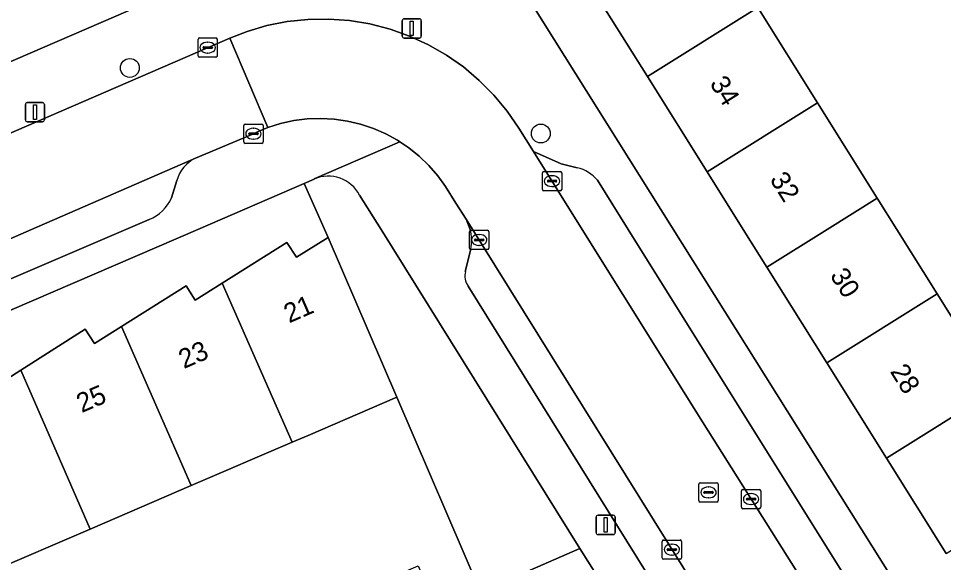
# Model space of a CAD drawing. Extents: x 159352 to 160617, y 385888 to 387323.
# Drawn here: x 159685.66 to 159733.61, y 386232.72 to 386260.95 of the extents above; entities that cross this region are included whole.
import ezdxf

# ---------------------------------------------------------------- set-up
doc = ezdxf.new("R2010")
doc.units = 0
for name, color, linetype in [('IMGEO_Boom', 7, 'Continuous'), ('IMGEO_Erf', 7, 'Continuous'), ('IMGEO_Groenvoorziening', 7, 'Continuous'), ('IMGEO_Kolk', 7, 'Continuous'), ('IMGEO_Lichtmast', 7, 'Continuous'), ('IMGEO_Pand', 7, 'Continuous'), ('IMGEO_Pand_nummerreeks', 7, 'Continuous'), ('IMGEO_Parkeervlak_open', 7, 'Continuous'), ('IMGEO_Rijbaan_lokaal_open', 7, 'Continuous'), ('IMGEO_Rioolput', 7, 'Continuous'), ('IMGEO_Voetpad_open', 7, 'Continuous')]:
    doc.layers.add(name, color=color, linetype=linetype)

msp = doc.modelspace()

# ---------------------------------------------------------------- linework, layer by layer
at = {"layer": 'IMGEO_Boom'}
for centre in [(159691.433, 386258.38), (159712.735, 386254.974)]:
    msp.add_circle(centre, 0.489, dxfattribs=at)
at = {"layer": 'IMGEO_Erf'}
for points in [[(159684.675, 386306.593), (159662.967, 386297.224), (159666.737, 386288.494), (159668.247, 386284.999), (159665.868, 386283.972), (159666.716, 386282.012), (159669.102, 386283.045), (159670.095, 386280.751), (159671.505, 386277.494), (159672.931, 386274.199), (159673.89, 386271.984), (159671.504, 386270.951), (159672.472, 386268.715), (159674.858, 386269.748), (159676.268, 386266.491), (159677.694, 386263.196), (159675.308, 386262.163), (159678.131, 386255.638), (159699.462, 386264.867)], [(159747.163, 386257.648), (159744.743, 386256.118), (159742.651, 386259.427), (159740.817, 386262.329), (159743.237, 386263.859), (159740.975, 386267.538), (159738.555, 386266.008), (159736.465, 386269.315), (159734.629, 386272.219), (159737.049, 386273.749), (159735.739, 386275.442), (159732.563, 386280.372), (159730.296, 386278.912), (159730.161, 386279.136), (159709.565, 386266.048), (159737.124, 386222.064)], [(159733.75, 386233.191), (159730.653, 386238.14), (159727.557, 386243.087), (159724.456, 386248.041), (159723.23, 386250), (159721.363, 386252.982), (159718.266, 386257.931), (159715.091, 386263.004), (159719.33, 386265.657), (159720.811, 386266.583), (159721.092, 386266.135), (159723.603, 386267.744), (159726.269, 386263.593), (159723.762, 386261.867), (159723.986, 386261.509), (159727.082, 386256.56), (159730.174, 386251.619), (159731.187, 386250), (159733.275, 386246.664), (159736.37, 386241.716)], [(159684.366, 386241.806), (159685.781, 386242.704), (159689.113, 386244.818), (159689.592, 386244.075), (159690.997, 386244.961), (159694.346, 386247.073), (159694.816, 386246.331), (159696.21, 386247.21), (159699.566, 386249.327), (159700.068, 386248.566), (159701.706, 386249.577), (159700.471, 386252.381), (159694.949, 386250), (159599.575, 386208.876)], [(159678.381, 386217.729), (159690.481, 386222.933), (159689.474, 386225.274), (159692.711, 386226.667), (159695.916, 386228.046), (159696.923, 386225.705), (159700.95, 386227.437), (159699.943, 386229.778), (159703.257, 386231.204), (159706.385, 386232.55), (159707.392, 386230.209), (159709.611, 386231.2), (159705.267, 386241.292), (159700.675, 386239.316), (159699.843, 386238.958), (159694.613, 386236.708), (159689.374, 386234.454), (159684.117, 386232.192)]]:
    msp.add_lwpolyline(points, dxfattribs=at)
at = {"layer": 'IMGEO_Groenvoorziening'}
msp.add_lwpolyline([(159700.986, 386252.613), (159700.471, 386252.381), (159701.706, 386249.577), (159705.267, 386241.292), (159709.611, 386231.2), (159714.762, 386233.446), (159704.452, 386250), (159703.344, 386251.779)], dxfattribs=at)
msp.add_arc((159701.713, 386250.919), 1.844, 27.8113, 113.2324, dxfattribs=at)
at = {"layer": 'IMGEO_Kolk'}
for p, q in [((159694.966, 386259.007), (159694.966, 386259.859)), ((159695.041, 386259.933), (159695.893, 386259.933)), ((159695.967, 386259.859), (159695.967, 386259.007)), ((159695.225, 386259.427), (159695.225, 386259.439)), ((159695.663, 386259.39), (159695.265, 386259.39)), ((159695.268, 386259.476), (159695.666, 386259.476)), ((159695.454, 386259.713), (159695.479, 386259.713)), ((159695.709, 386259.439), (159695.709, 386259.427)), ((159695.893, 386258.933), (159695.041, 386258.933)), ((159695.477, 386259.153), (159695.452, 386259.153)), ((159697.339, 386254.541), (159697.339, 386255.393)), ((159697.414, 386255.467), (159698.266, 386255.467)), ((159697.827, 386255.247), (159697.852, 386255.247)), ((159698.34, 386255.393), (159698.34, 386254.541)), ((159697.598, 386254.961), (159697.598, 386254.973)), ((159698.036, 386254.924), (159697.638, 386254.924)), ((159697.641, 386255.01), (159698.039, 386255.01)), ((159697.85, 386254.687), (159697.825, 386254.687)), ((159698.082, 386254.973), (159698.082, 386254.961)), ((159698.266, 386254.467), (159697.414, 386254.467)), ((159712.817, 386252.08), (159712.817, 386252.932)), ((159712.892, 386253.006), (159713.744, 386253.006)), ((159713.305, 386252.786), (159713.33, 386252.786)), ((159713.818, 386252.932), (159713.818, 386252.08)), ((159713.076, 386252.5), (159713.076, 386252.512)), ((159713.514, 386252.463), (159713.116, 386252.463)), ((159713.119, 386252.549), (159713.517, 386252.549)), ((159713.328, 386252.226), (159713.303, 386252.226)), ((159713.56, 386252.512), (159713.56, 386252.5)), ((159713.744, 386252.006), (159712.892, 386252.006)), ((159709.04, 386249.028), (159709.04, 386249.88)), ((159709.115, 386249.954), (159709.967, 386249.954)), ((159710.041, 386249.88), (159710.041, 386249.028)), ((159709.299, 386249.448), (159709.299, 386249.46)), ((159709.737, 386249.411), (159709.339, 386249.411)), ((159709.342, 386249.497), (159709.74, 386249.497)), ((159709.528, 386249.734), (159709.553, 386249.734)), ((159709.783, 386249.46), (159709.783, 386249.448)), ((159709.967, 386248.954), (159709.115, 386248.954)), ((159709.551, 386249.174), (159709.526, 386249.174)), ((159723.134, 386235.585), (159723.134, 386236.437)), ((159723.209, 386236.511), (159724.061, 386236.511)), ((159724.135, 386236.437), (159724.135, 386235.585)), ((159723.393, 386236.005), (159723.393, 386236.017)), ((159723.831, 386235.968), (159723.433, 386235.968)), ((159723.436, 386236.054), (159723.834, 386236.054)), ((159723.622, 386236.291), (159723.647, 386236.291)), ((159723.877, 386236.017), (159723.877, 386236.005)), ((159724.061, 386235.511), (159723.209, 386235.511)), ((159723.645, 386235.731), (159723.62, 386235.731)), ((159719.027, 386232.96), (159719.027, 386233.812)), ((159719.102, 386233.886), (159719.954, 386233.886)), ((159719.515, 386233.666), (159719.54, 386233.666)), ((159720.028, 386233.812), (159720.028, 386232.96)), ((159719.286, 386233.38), (159719.286, 386233.392)), ((159719.724, 386233.343), (159719.326, 386233.343)), ((159719.329, 386233.429), (159719.727, 386233.429)), ((159719.538, 386233.106), (159719.513, 386233.106)), ((159719.77, 386233.392), (159719.77, 386233.38)), ((159719.954, 386232.886), (159719.102, 386232.886))]:
    msp.add_line(p, q, dxfattribs=at)
for points in [[(159694.966, 386259.007), (159694.966, 386259.859)], [(159695.041, 386259.933), (159695.893, 386259.933)], [(159695.967, 386259.859), (159695.967, 386259.007)], [(159695.893, 386258.933), (159695.041, 386258.933)], [(159697.339, 386254.541), (159697.339, 386255.393)], [(159697.414, 386255.467), (159698.266, 386255.467)], [(159698.34, 386255.393), (159698.34, 386254.541)], [(159698.266, 386254.467), (159697.414, 386254.467)], [(159712.817, 386252.08), (159712.817, 386252.932)], [(159712.892, 386253.006), (159713.744, 386253.006)], [(159713.818, 386252.932), (159713.818, 386252.08)], [(159713.744, 386252.006), (159712.892, 386252.006)], [(159709.04, 386249.028), (159709.04, 386249.88)], [(159709.115, 386249.954), (159709.967, 386249.954)], [(159710.041, 386249.88), (159710.041, 386249.028)], [(159709.967, 386248.954), (159709.115, 386248.954)], [(159723.134, 386235.585), (159723.134, 386236.437)], [(159723.209, 386236.511), (159724.061, 386236.511)], [(159724.135, 386236.437), (159724.135, 386235.585)], [(159724.061, 386235.511), (159723.209, 386235.511)], [(159719.027, 386232.96), (159719.027, 386233.812)], [(159719.102, 386233.886), (159719.954, 386233.886)], [(159720.028, 386233.812), (159720.028, 386232.96)], [(159719.954, 386232.886), (159719.102, 386232.886)]]:
    msp.add_lwpolyline(points, dxfattribs=at)
for centre, radius, start, end in [((159695.043, 386259.857), 0.0765, 91.552, 178.448), ((159695.043, 386259.857), 0.0765, 91.552, 178.448), ((159695.891, 386259.857), 0.0765, 1.552, 88.448), ((159695.891, 386259.857), 0.0765, 1.552, 88.448), ((159695.265, 386259.436), 0.0403, 85.8775, 175.7526), ((159695.262, 386259.426), 0.0366, 178.938, 274.7102), ((159695.666, 386259.433), 0.043, 264.8664, 352.4533), ((159695.67, 386259.438), 0.0386, 1.7309, 96.639), ((159695.043, 386259.009), 0.0765, 181.552, 268.448), ((159695.043, 386259.009), 0.0765, 181.552, 268.448), ((159695.891, 386259.009), 0.0765, 271.552, 358.448), ((159695.891, 386259.009), 0.0765, 271.552, 358.448), ((159697.416, 386255.391), 0.0765, 91.552, 178.448), ((159697.416, 386255.391), 0.0765, 91.552, 178.448), ((159698.264, 386255.391), 0.0765, 1.552, 88.448), ((159698.264, 386255.391), 0.0765, 1.552, 88.448), ((159697.638, 386254.97), 0.0403, 85.8775, 175.7526), ((159697.635, 386254.96), 0.0366, 178.938, 274.7102), ((159698.039, 386254.967), 0.043, 264.8664, 352.4533), ((159698.043, 386254.972), 0.0386, 1.7309, 96.639), ((159697.416, 386254.543), 0.0765, 181.552, 268.448), ((159697.416, 386254.543), 0.0765, 181.552, 268.448), ((159698.264, 386254.543), 0.0765, 271.552, 358.448), ((159698.264, 386254.543), 0.0765, 271.552, 358.448), ((159712.894, 386252.93), 0.0765, 91.552, 178.448), ((159712.894, 386252.93), 0.0765, 91.552, 178.448), ((159713.742, 386252.93), 0.0765, 1.552, 88.448), ((159713.742, 386252.93), 0.0765, 1.552, 88.448), ((159713.116, 386252.509), 0.0403, 85.8775, 175.7526), ((159713.113, 386252.499), 0.0366, 178.938, 274.7102), ((159713.517, 386252.506), 0.043, 264.8664, 352.4533), ((159713.521, 386252.511), 0.0386, 1.7309, 96.639), ((159712.894, 386252.082), 0.0765, 181.552, 268.448), ((159712.894, 386252.082), 0.0765, 181.552, 268.448), ((159713.742, 386252.082), 0.0765, 271.552, 358.448), ((159713.742, 386252.082), 0.0765, 271.552, 358.448), ((159709.117, 386249.878), 0.0765, 91.552, 178.448), ((159709.117, 386249.878), 0.0765, 91.552, 178.448), ((159709.965, 386249.878), 0.0765, 1.552, 88.448), ((159709.965, 386249.878), 0.0765, 1.552, 88.448), ((159709.339, 386249.457), 0.0403, 85.8775, 175.7526), ((159709.336, 386249.447), 0.0366, 178.938, 274.7102), ((159709.74, 386249.454), 0.043, 264.8664, 352.4533), ((159709.744, 386249.459), 0.0386, 1.7309, 96.639), ((159709.117, 386249.03), 0.0765, 181.552, 268.448), ((159709.117, 386249.03), 0.0765, 181.552, 268.448), ((159709.965, 386249.03), 0.0765, 271.552, 358.448), ((159709.965, 386249.03), 0.0765, 271.552, 358.448), ((159723.211, 386236.435), 0.0765, 91.552, 178.448), ((159723.211, 386236.435), 0.0765, 91.552, 178.448), ((159724.059, 386236.435), 0.0765, 1.552, 88.448), ((159724.059, 386236.435), 0.0765, 1.552, 88.448), ((159723.433, 386236.014), 0.0403, 85.8775, 175.7526), ((159723.43, 386236.004), 0.0366, 178.938, 274.7102), ((159723.834, 386236.011), 0.043, 264.8664, 352.4533), ((159723.838, 386236.016), 0.0386, 1.7309, 96.639), ((159723.211, 386235.587), 0.0765, 181.552, 268.448), ((159723.211, 386235.587), 0.0765, 181.552, 268.448), ((159724.059, 386235.587), 0.0765, 271.552, 358.448), ((159724.059, 386235.587), 0.0765, 271.552, 358.448), ((159719.104, 386233.81), 0.0765, 91.552, 178.448), ((159719.104, 386233.81), 0.0765, 91.552, 178.448), ((159719.952, 386233.81), 0.0765, 1.552, 88.448), ((159719.952, 386233.81), 0.0765, 1.552, 88.448), ((159719.326, 386233.389), 0.0403, 85.8775, 175.7526), ((159719.323, 386233.379), 0.0366, 178.938, 274.7102), ((159719.727, 386233.386), 0.043, 264.8664, 352.4533), ((159719.731, 386233.391), 0.0386, 1.7309, 96.639), ((159719.104, 386232.962), 0.0765, 181.552, 268.448), ((159719.104, 386232.962), 0.0765, 181.552, 268.448), ((159719.952, 386232.962), 0.0765, 271.552, 358.448), ((159719.952, 386232.962), 0.0765, 271.552, 358.448)]:
    msp.add_arc(centre, radius, start, end, dxfattribs=at)
for centre, major_axis, ratio, start_param, end_param in [((159695.453, 386259.433), (-0.387, 0.002), 0.722429, 4.712389, 7.853982), ((159695.478, 386259.433), (-0.39, 0.002), 0.717154, 1.570796, 4.712389), ((159697.826, 386254.967), (-0.387, 0.002), 0.722429, 4.712389, 7.853982), ((159697.851, 386254.967), (-0.39, 0.002), 0.717154, 1.570796, 4.712389), ((159713.304, 386252.506), (-0.387, 0.002), 0.722429, 4.712389, 7.853982), ((159713.329, 386252.506), (-0.39, 0.002), 0.717154, 1.570796, 4.712389), ((159709.527, 386249.454), (-0.387, 0.002), 0.722429, 4.712389, 7.853982), ((159709.552, 386249.454), (-0.39, 0.002), 0.717154, 1.570796, 4.712389), ((159723.621, 386236.011), (-0.387, 0.002), 0.722429, 4.712389, 7.853982), ((159723.646, 386236.011), (-0.39, 0.002), 0.717154, 1.570796, 4.712389), ((159719.514, 386233.386), (-0.387, 0.002), 0.722429, 4.712389, 7.853982), ((159719.539, 386233.386), (-0.39, 0.002), 0.717154, 1.570796, 4.712389)]:
    msp.add_ellipse(centre, major_axis=major_axis, ratio=ratio, start_param=start_param, end_param=end_param, dxfattribs=at)
at = {"layer": 'IMGEO_Lichtmast'}
for p, q in [((159705.551, 386260.03), (159705.551, 386260.83)), ((159705.551, 386260.83), (159705.551, 386260.03)), ((159705.651, 386260.93), (159706.441, 386260.93)), ((159706.441, 386260.93), (159705.651, 386260.93)), ((159706.541, 386260.83), (159706.541, 386260.03)), ((159706.541, 386260.03), (159706.541, 386260.83)), ((159706.441, 386259.93), (159705.651, 386259.93)), ((159705.651, 386259.93), (159706.441, 386259.93)), ((159686.015, 386255.685), (159686.015, 386256.485)), ((159686.015, 386256.485), (159686.015, 386255.685)), ((159686.115, 386256.585), (159686.905, 386256.585)), ((159686.905, 386256.585), (159686.115, 386256.585)), ((159687.005, 386256.485), (159687.005, 386255.685)), ((159687.005, 386255.685), (159687.005, 386256.485)), ((159686.905, 386255.585), (159686.115, 386255.585)), ((159686.115, 386255.585), (159686.905, 386255.585)), ((159715.601, 386234.271), (159715.601, 386235.071)), ((159715.601, 386235.071), (159715.601, 386234.271)), ((159715.701, 386235.171), (159716.491, 386235.171)), ((159716.491, 386235.171), (159715.701, 386235.171)), ((159716.591, 386235.071), (159716.591, 386234.271)), ((159716.591, 386234.271), (159716.591, 386235.071)), ((159716.491, 386234.171), (159715.701, 386234.171)), ((159715.701, 386234.171), (159716.491, 386234.171))]:
    msp.add_line(p, q, dxfattribs=at)
for points in [[(159705.971, 386260.805), (159706.121, 386260.805), (159706.121, 386260.055), (159705.971, 386260.055), (159705.971, 386260.805)], [(159686.435, 386256.46), (159686.585, 386256.46), (159686.585, 386255.71), (159686.435, 386255.71), (159686.435, 386256.46)], [(159716.021, 386235.046), (159716.171, 386235.046), (159716.171, 386234.296), (159716.021, 386234.296), (159716.021, 386235.046)]]:
    msp.add_lwpolyline(points, dxfattribs=at)
for centre, start, end in [((159705.651, 386260.83), 90, 180), ((159705.651, 386260.83), 90, 180), ((159706.441, 386260.83), 0, 90), ((159706.441, 386260.83), 360, 90), ((159705.651, 386260.03), 180, 270), ((159705.651, 386260.03), 180, 270), ((159706.441, 386260.03), 270, 0), ((159706.441, 386260.03), 270, 0), ((159686.115, 386256.485), 90, 180), ((159686.115, 386256.485), 90, 180), ((159686.905, 386256.485), 0, 90), ((159686.905, 386256.485), 360, 90), ((159686.115, 386255.685), 180, 270), ((159686.115, 386255.685), 180, 270), ((159686.905, 386255.685), 270, 0), ((159686.905, 386255.685), 270, 0), ((159715.701, 386235.071), 90, 180), ((159715.701, 386235.071), 90, 180), ((159716.491, 386235.071), 0, 90), ((159716.491, 386235.071), 360, 90), ((159715.701, 386234.271), 180, 270), ((159715.701, 386234.271), 180, 270), ((159716.491, 386234.271), 270, 0), ((159716.491, 386234.271), 270, 0)]:
    msp.add_arc(centre, 0.1, start, end, dxfattribs=at)
at = {"layer": 'IMGEO_Pand'}
for points in [[(159721.092, 386266.135), (159720.811, 386266.583), (159719.33, 386265.657), (159715.091, 386263.004), (159718.266, 386257.931), (159723.986, 386261.509), (159723.762, 386261.867), (159726.269, 386263.593), (159723.603, 386267.744)], [(159718.266, 386257.931), (159721.363, 386252.982), (159727.082, 386256.56), (159723.986, 386261.509)], [(159727.587, 386250), (159730.174, 386251.619), (159727.082, 386256.56), (159721.363, 386252.982), (159723.23, 386250), (159724.456, 386248.041)], [(159724.456, 386248.041), (159727.557, 386243.087), (159733.275, 386246.664), (159731.187, 386250), (159730.174, 386251.619), (159727.587, 386250)], [(159701.706, 386249.577), (159700.068, 386248.566), (159699.566, 386249.327), (159696.21, 386247.21), (159699.843, 386238.958), (159700.675, 386239.316), (159705.267, 386241.292)], [(159696.21, 386247.21), (159694.816, 386246.331), (159694.346, 386247.073), (159690.997, 386244.961), (159694.613, 386236.708), (159699.843, 386238.958)], [(159727.557, 386243.087), (159730.653, 386238.14), (159736.37, 386241.716), (159733.275, 386246.664)], [(159690.997, 386244.961), (159689.592, 386244.075), (159689.113, 386244.818), (159685.781, 386242.704), (159689.374, 386234.454), (159694.613, 386236.708)], [(159685.781, 386242.704), (159684.366, 386241.806), (159683.888, 386242.553), (159680.559, 386240.462), (159684.117, 386232.192), (159689.374, 386234.454)], [(159730.653, 386238.14), (159733.75, 386233.191), (159739.467, 386236.768), (159736.37, 386241.716)]]:
    msp.add_lwpolyline(points, close=True, dxfattribs=at)
at = {"layer": 'IMGEO_Parkeervlak_open'}
for points in [[(159694.84, 386253.699), (159686.334, 386250), (159681.73, 386247.998), (159678.398, 386246.561), (159679.147, 386244.823), (159691.231, 386250)], [(159714.626, 386253.203), (159713.789, 386253.396), (159712.353, 386254.051), (159714.88, 386250), (159721.113, 386240.01), (159731.901, 386222.896)], [(159693.593, 386251.643), (159693.863, 386252.544)], [(159731.921, 386226.535), (159717.271, 386250), (159715.678, 386252.552)], [(159691.231, 386250), (159692.435, 386250.516)], [(159708.862, 386250.524), (159709.076, 386250)], [(159728.997, 386218.179), (159728.35, 386219.221), (159708.862, 386250.524)], [(159709.103, 386248.984), (159708.823, 386247.818)], [(159708.962, 386247.06), (159725.996, 386219.672)]]:
    msp.add_lwpolyline(points, dxfattribs=at)
for centre, radius, start, end in [((159695.672, 386252.005), 1.887, 116.1468, 163.3983), ((159714.124, 386251.217), 2.049, 40.6761, 75.8237), ((159691.642, 386252.489), 2.126, 291.8918, 336.5537), ((159706.951, 386249.435), 2.199, 348.159, 14.8855), ((159709.793, 386247.604), 0.993, 167.5695, 213.2131)]:
    msp.add_arc(centre, radius, start, end, dxfattribs=at)
at = {"layer": 'IMGEO_Rijbaan_lokaal_open'}
for points in [[(159731.901, 386222.896), (159721.113, 386240.01), (159714.88, 386250), (159712.353, 386254.051), (159711.601, 386255.256), (159710.991, 386256.142), (159710.305, 386256.971), (159709.547, 386257.735), (159708.724, 386258.428), (159707.842, 386259.044), (159706.909, 386259.58), (159705.931, 386260.03), (159704.918, 386260.391), (159703.876, 386260.66), (159702.814, 386260.834), (159701.741, 386260.914), (159700.665, 386260.897), (159699.595, 386260.784), (159698.539, 386260.576), (159697.507, 386260.274), (159696.609, 386259.927), (159698.584, 386255.284), (159699.25, 386255.494), (159699.932, 386255.644), (159700.625, 386255.732), (159701.323, 386255.757), (159702.02, 386255.721), (159702.711, 386255.622), (159703.391, 386255.462), (159704.054, 386255.242), (159704.694, 386254.963), (159705.307, 386254.628), (159705.433, 386254.544), (159705.887, 386254.24), (159706.431, 386253.802), (159706.933, 386253.317), (159707.39, 386252.789), (159707.798, 386252.222), (159708.336, 386251.369), (159708.862, 386250.524), (159728.35, 386219.221)], [(159664.679, 386240.646), (159674.955, 386245.077), (159678.398, 386246.561), (159681.73, 386247.998), (159686.334, 386250), (159694.84, 386253.699), (159697.839, 386254.968), (159698.076, 386255.078), (159698.584, 386255.284), (159696.609, 386259.927), (159678.479, 386252.07), (159675.018, 386250.574), (159673.692, 386250), (159656.655, 386242.648), (159656.656, 386242.615), (159641.394, 386236.065)]]:
    msp.add_lwpolyline(points, dxfattribs=at)
at = {"layer": 'IMGEO_Rioolput'}
for p, q in [((159721.004, 386236.857), (159721.856, 386236.857)), ((159720.929, 386235.931), (159720.929, 386236.783)), ((159721.188, 386236.351), (159721.188, 386236.363)), ((159721.231, 386236.4), (159721.629, 386236.4)), ((159721.417, 386236.637), (159721.442, 386236.637)), ((159721.672, 386236.363), (159721.672, 386236.351)), ((159721.93, 386236.783), (159721.93, 386235.931)), ((159721.626, 386236.314), (159721.228, 386236.314)), ((159721.44, 386236.077), (159721.415, 386236.077)), ((159721.856, 386235.857), (159721.004, 386235.857))]:
    msp.add_line(p, q, dxfattribs=at)
for points in [[(159721.004, 386236.857), (159721.856, 386236.857)], [(159720.929, 386235.931), (159720.929, 386236.783)], [(159721.93, 386236.783), (159721.93, 386235.931)], [(159721.856, 386235.857), (159721.004, 386235.857)]]:
    msp.add_lwpolyline(points, dxfattribs=at)
for centre, radius, start, end in [((159721.006, 386236.781), 0.0765, 91.552, 178.448), ((159721.006, 386236.781), 0.0765, 91.552, 178.448), ((159721.854, 386236.781), 0.0765, 1.552, 88.448), ((159721.854, 386236.781), 0.0765, 1.552, 88.448), ((159721.228, 386236.36), 0.0403, 85.8775, 175.7526), ((159721.225, 386236.35), 0.0366, 178.938, 274.7102), ((159721.629, 386236.357), 0.043, 264.8664, 352.4533), ((159721.633, 386236.362), 0.0386, 1.7309, 96.639), ((159721.006, 386235.933), 0.0765, 181.552, 268.448), ((159721.006, 386235.933), 0.0765, 181.552, 268.448), ((159721.854, 386235.933), 0.0765, 271.552, 358.448), ((159721.854, 386235.933), 0.0765, 271.552, 358.448)]:
    msp.add_arc(centre, radius, start, end, dxfattribs=at)
for centre, major_axis, ratio, start_param, end_param in [((159721.416, 386236.357), (-0.387, 0.002), 0.722429, 4.712389, 7.853982), ((159721.441, 386236.357), (-0.39, 0.002), 0.717154, 1.570796, 4.712389)]:
    msp.add_ellipse(centre, major_axis=major_axis, ratio=ratio, start_param=start_param, end_param=end_param, dxfattribs=at)
at = {"layer": 'IMGEO_Voetpad_open'}
for points in [[(159709.565, 386266.048), (159709.001, 386266.959), (159708.189, 386268.272), (159699.462, 386264.867), (159678.131, 386255.638), (159676.842, 386255.08), (159665.102, 386250), (159655.763, 386245.959), (159655.677, 386245.872), (159650.446, 386243.55)], [(159737.124, 386222.064), (159709.565, 386266.048)], [(159678.479, 386252.07), (159696.609, 386259.927), (159697.507, 386260.274), (159698.539, 386260.576), (159699.595, 386260.784), (159700.665, 386260.897), (159701.741, 386260.914), (159702.814, 386260.834), (159703.876, 386260.66), (159704.918, 386260.391), (159705.931, 386260.03), (159706.909, 386259.58), (159707.842, 386259.044), (159708.724, 386258.428), (159709.547, 386257.735), (159710.305, 386256.971), (159710.991, 386256.142), (159711.601, 386255.256), (159712.353, 386254.051), (159713.789, 386253.396), (159714.626, 386253.203)], [(159705.433, 386254.544), (159705.307, 386254.628), (159704.694, 386254.963), (159704.054, 386255.242), (159703.391, 386255.462), (159702.711, 386255.622), (159702.02, 386255.721), (159701.323, 386255.757), (159700.625, 386255.732), (159699.932, 386255.644), (159699.25, 386255.494), (159698.584, 386255.284), (159698.076, 386255.078), (159697.839, 386254.968), (159694.84, 386253.699)], [(159599.575, 386208.876), (159694.949, 386250), (159700.471, 386252.381), (159700.986, 386252.613), (159700.992, 386252.628), (159705.433, 386254.544)], [(159708.336, 386251.369), (159707.798, 386252.222), (159707.39, 386252.789), (159706.933, 386253.317), (159706.431, 386253.802), (159705.887, 386254.24), (159705.433, 386254.544), (159700.992, 386252.628), (159700.986, 386252.613)], [(159693.863, 386252.544), (159693.593, 386251.643)], [(159715.678, 386252.552), (159717.271, 386250), (159731.921, 386226.535)], [(159703.344, 386251.779), (159704.452, 386250), (159714.762, 386233.446), (159715.586, 386232.137), (159724.116, 386218.496), (159725.996, 386219.672), (159708.962, 386247.06)], [(159709.076, 386250), (159708.862, 386250.524), (159708.336, 386251.369)], [(159692.435, 386250.516), (159691.231, 386250), (159679.147, 386244.823), (159679.332, 386244.41), (159675.869, 386242.916), (159675.708, 386243.331), (159660.393, 386236.7), (159660.572, 386236.289), (159657.111, 386234.796), (159656.936, 386235.216), (159641.701, 386228.667), (159641.868, 386228.269), (159638.432, 386226.756), (159638.262, 386227.153), (159623.466, 386220.812), (159623.657, 386220.412), (159620.194, 386218.926), (159620.013, 386219.343), (159605.603, 386213.141)], [(159708.823, 386247.818), (159709.103, 386248.984)]]:
    msp.add_lwpolyline(points, dxfattribs=at)
msp.add_lwpolyline([(159715.586, 386232.137), (159714.762, 386233.446), (159709.611, 386231.2), (159710.205, 386229.812)], close=True, dxfattribs=at)
for centre, radius, start, end in [((159695.672, 386252.005), 1.887, 116.1468, 163.3983), ((159714.124, 386251.217), 2.049, 40.6761, 75.8237), ((159701.713, 386250.919), 1.844, 27.8113, 113.2324), ((159691.642, 386252.489), 2.126, 291.8918, 336.5537), ((159706.951, 386249.435), 2.199, 348.159, 14.8855), ((159709.793, 386247.604), 0.993, 167.5695, 213.2131)]:
    msp.add_arc(centre, radius, start, end, dxfattribs=at)

# ---------------------------------------------------------------- texts
at = {"layer": 'IMGEO_Pand_nummerreeks'}
for s, rotation, p in [('34', 302.0411, (159721.464, 386257.572)), ('32', 302.0411, (159724.578, 386252.595)), ('30', 302.0411, (159727.698, 386247.61)), ('21', 23.485, (159699.686, 386245.122)), ('23', 23.485, (159694.234, 386242.754)), ('28', 302.0411, (159730.814, 386242.631)), ('25', 23.2383, (159688.934, 386240.469))]:
    msp.add_text(s, height=1, rotation=rotation, dxfattribs=at).set_placement(p)

doc.saveas('drawing.dxf')
